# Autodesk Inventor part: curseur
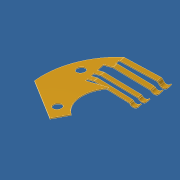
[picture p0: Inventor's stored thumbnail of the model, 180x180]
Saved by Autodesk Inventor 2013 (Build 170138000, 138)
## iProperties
Created: 2011-07
Part Number: curseur
Document SubType Name: Tôlerie
Designer: didierf
Density: 8.47 g/cm^3
Material: Laiton (jaune doux)
Mass: 0.0357038 g
Surface Area: 0.921068 cm^2
Volume: 0.00421532 cm^3
Sheet Metal Rule: Par défaut
Author: didierf
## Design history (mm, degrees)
sketch "Esquisse3"
  geometry: L1 (-14.379, 11.345)-(1.25, 18.566); L2 (1.25, 18.566)-(10.479, -1.409); L3 (10.479, -1.409)-(-5.149, -8.63); L4 (-5.149, -8.63)-(-14.379, 11.345); L5 (4.506, -11.411)-(4.506, -32.563); 1 other entity
  constraints: 2 end point, 1 vertical, 2 other
  dimensions: "d19" = 17.216 distance of L1.start L1.end; "d84" = 24.7991 deg angle of L5 L4
  node "Image2"
sketch "tracé"
  geometry: L1 (3.886, -3.147)-(6.941, 0.626); L2 (0, -41.976)-(0, 8.25); L3 (-3.534, -3.184)-(-5.423, -0.851); L4 (-5.774, -0.814)-(-6.941, 0.626); L5 (0, 0)-(-3.552, -3.519); C1 r 2.5 at (0, 0); C2 r 0.5 at (4.25, -0.7); C3 r 0.5 at (4.25, 5.1); C4 r 2.95 at (0, 0); C5 r 0.96 at (3, 4); A1 r 5 centre (0, 0) between (-3.552, -3.519) and (3.886, -3.147); A2 r 8.25 centre (0, 0) between (7.243, 3.95) and (-7.243, 3.95); A3 r 3 centre (-4.609, 2.514) between (-7.243, 3.95) and (-6.941, 0.626); A4 r 3 centre (4.609, 2.514) between (6.941, 0.626) and (7.243, 3.95); A5 r 0.25 centre (-3.728, -3.341) between (-3.552, -3.519) and (-3.534, -3.184); A6 r 0.25 centre (-5.617, -1.009) between (-5.423, -0.851) and (-5.774, -0.814); A7 r 7.95 centre (0, 0) between (7.603, 2.323) and (-7.603, 2.323); 1 further point
  constraints: 17 point on circle, 12 centre point, 10 end point, 9 tangent, 5 coincident, 1 parallel, 1 point on line, 1 vertical
  dimensions: "d53" = 10 diameter of A1; "d54" = 5 diameter of C1; "d57" = 8.25 radius of A2; "d60" = 6 diameter of A3; "d61" = 6 diameter of A4; "d66" = 78 deg angle of L1 L4; "d67" = 0.25 radius of A5; "d68" = 0.25 radius of A6; "d69" = 0.25 distance between parallel lines of L4 L3; "d70" = 3.5 distance of L4.start L5.end; "d71" = 39 deg angle of L1 L2 (derived); "d104" = 1 diameter of C2; "d105" = 1 diameter of C3; "d106" = 4.25 horizontal distance of C2.centre point (0, 0); "d107" = 0.7 vertical distance of C2.centre point (0, 0); "d108" = 5.8 distance of C2.centre C3.centre; "d109" = 4.25 horizontal distance of C3.centre point (0, 0) (derived); "d110" = 0.3 radial gap between concentric circles of A7 A2; "d114" = 5.9 diameter of C4; "d115" = 1.92 diameter of C5; "d117" = 3 distance from line of C5.centre L2; "d120" = 4 vertical distance of C5.centre point (0, 0)
sketch "piece_a_plat"
  geometry: L1 (1.033, 3.091)-(3.317, 3.6); L2 (3.317, 3.6)-(3.244, 3.926); L3 (3.244, 3.926)-(-1.948, 2.769); L4 (2.7, 6.366)-(-2.98, 5.101); L5 (-3.587, 6.707)-(1.418, 7.822); L6 (-2.489, 4.186)-(2.918, 5.39); L7 (1.642, 7.258)-(-3.457, 6.121); L8 (1.751, 6.77)-(-3.111, 5.686); L9 (1.751, 6.77)-(1.642, 7.258); L10 (-3.587, 6.707)-(-3.457, 6.121); L11 (-3.111, 5.686)-(-2.98, 5.101); L12 (3.135, 4.414)-(-2.056, 3.258); L13 (3.026, 4.902)-(-2.38, 3.698); L14 (1.277, 6.049)-(1.146, 6.635); L15 (1.037, 7.123)-(0.907, 7.709); L16 (-2.489, 4.186)-(-2.38, 3.698); L17 (-2.056, 3.258)-(-1.948, 2.769); L18 (2.918, 5.39)-(2.7, 6.366); L19 (2.57, 3.776)-(2.462, 4.264); L20 (2.353, 4.752)-(2.244, 5.24); L21 (3.317, 3.6)-(3.244, 3.926); L22 (3.135, 4.414)-(3.026, 4.902); L23 (7.51, 2.609)-(4.243, -2.596); L24 (4.243, -2.596)-(2.68, -1.616); L25 (1.033, 3.091)-(1.066, 2.942); L26 (-2.649, 6.916)-(-2.518, 6.331); L27 (-2.159, 5.898)-(-2.028, 5.313); L28 (-1.515, 4.403)-(-1.407, 3.915); L29 (-1.089, 3.473)-(-0.98, 2.985); L30 (-3.587, 6.707)-(-2.649, 6.916); L31 (-2.056, 3.258)-(-1.089, 3.473); L32 (-3.118, 6.812)-(-2.988, 6.226); L33 (-2.633, 5.793)-(-2.503, 5.207); L34 (-1.995, 4.296)-(-1.886, 3.808); L35 (-1.573, 3.365)-(-1.464, 2.877); C1 r 0.5 at (4.25, 5.1) reference; C2 r 0.5 at (4.25, 5.1); C3 r 0.5 at (4.25, -0.7) reference; C4 r 0.5 at (4.25, -0.7); A1 r 7.95 centre (0, 0) between (7.603, 2.323) and (-7.603, 2.323) reference; A2 r 7.95 centre (0, 0) between (7.51, 2.609) and (1.418, 7.822); A3 r 3.129 centre (0, 0) between (2.68, -1.616) and (1.066, 2.942); A4 r 3.129 centre (0, 0) between (-0.561, 3.079) and (-0.799, 3.025)
  constraints: 70 end point, 24 perpendicular, 24 point on line, 16 parallel, 7 point on circle, 5 centre point, 4 coincident, 3 concentric, 2 midpoint
  dimensions: "d145" = 0.6 distance of L5.start L7.end; "d146" = 0.6 distance of L8.end L4.end; "d147" = 0.5 distance of L6.start L13.end; "d148" = 0.5 distance of L12.end L3.end; "d222" = 1 distance between parallel lines of L6 L4; "d223" = 0.5 distance between parallel lines of L12 L13; "d224" = 0.5 distance between parallel lines of L7 L8
node "aplat"
feature "Pliage1patte1" dims "d150" = 0.1 (derived), "d151" = 0.05 (derived), "d152" = 0.2 (derived), "d153" = 0.1 (derived), "d154" = 3.42085, "d155" = 0.1 (derived), "Epaisseur" = 0.1, "JeuJointure" = 0.01
feature "Pliage1patte2" dims "d229" = 0.1 (derived), "d230" = 0.05 (derived), "d231" = 0.2 (derived), "d232" = 0.1 (derived), "d233" = 3.23759, "d234" = 0.1 (derived), "Epaisseur" = 0.1, "JeuJointure" = 0.01
sketch "Esquisse6"
  geometry: L1 (4.604, -0.5)-(4.604, 0) reference; L2 (4.604, 0)-(0, 0) reference; L3 (0, 0)-(0, -0.5) reference; L4 (0, -0.5)-(1.177, -0.5) reference; L5 (1.421, -0.5)-(4.604, -0.5) reference; L6 (1, 0)-(1, -0.5); A1 r 3.129 centre (1.299, -3.627) between (1.421, -0.5) and (1.177, -0.5) reference
  constraints: 2 end point, 2 point on line, 1 perpendicular
  dimensions: "d235" = 1 distance between parallel lines of L6 L3
feature "Pliage2patte1" sketch "Esquisse6" dims "d158" = 0.1 (derived), "d159" = 0.05 (derived), "d160" = 0.2 (derived), "d161" = 0.1 (derived), "d162" = 45 deg, "d163" = 0.1 (derived), "Epaisseur" = 0.1, "JeuJointure" = 0.01
sketch "Esquisse7"
  geometry: L1 (0, 0)-(0.943, 0) reference; L2 (0, 0.5)-(0, 0) reference; L3 (0.5, 0.5)-(0.5, 0); L4 (0.943, 0.5)-(0, 0.5) reference
  constraints: 2 end point, 2 point on line, 1 parallel
  dimensions: "d164" = 0.5 distance between parallel lines of L3 L2
feature "Pliage3patte1" sketch "Esquisse7" dims "d165" = 0.1 (derived), "d166" = 0.05 (derived), "d167" = 0.2 (derived), "d168" = 0.1 (derived), "d169" = 110 deg, "d170" = 0.4, "Epaisseur" = 0.1, "JeuJointure" = 0.01
sketch "Esquisse8"
  geometry: L1 (4.826, -0.5)-(4.826, 0) reference; L2 (4.826, 0)-(0, 0) reference; L3 (0, 0)-(0, -0.5) reference; L4 (0, -0.5)-(4.826, -0.5) reference; L5 (1, 0)-(1, -0.5)
  constraints: 2 end point, 2 point on line, 1 perpendicular
  dimensions: "d236" = 1 distance between parallel lines of L3 L5
feature "Pliage2patte2" sketch "Esquisse8" dims "d172" = 0.1 (derived), "d173" = 0.05 (derived), "d174" = 0.2 (derived), "d175" = 0.1 (derived), "d176" = 45 deg, "d177" = 0.1 (derived), "Epaisseur" = 0.1, "JeuJointure" = 0.01
sketch "Esquisse9"
  geometry: L1 (0.943, 0)-(0, 0) reference; L2 (0.943, 0.5)-(0.943, 0) reference; L3 (0, 0.5)-(0.943, 0.5) reference; L4 (0.443, 0)-(0.443, 0.5)
  constraints: 2 end point, 2 point on line, 1 perpendicular
  dimensions: "d237" = 0.5 distance between parallel lines of L2 L4
feature "Pliage3patte2" sketch "Esquisse9" dims "d179" = 0.1 (derived), "d180" = 0.05 (derived), "d181" = 0.2 (derived), "d182" = 0.1 (derived), "d183" = 110 deg, "d184" = 0.4, "Epaisseur" = 0.1, "JeuJointure" = 0.01
sketch "Esquisse10"
  geometry: L1 (-2.298, 6.061)-(-1.938, 5.581) reference; L2 (-6.177, 3.15)-(-5.817, 2.67); L3 (-2.763, 7.087)-(-2.403, 6.607) reference; L4 (-6.837, 4.03)-(-6.477, 3.55); L5 (-1.938, 5.581)-(-6.593, 2.088) reference; L6 (-6.282, 3.071)-(-2.298, 6.061) reference; L7 (-2.403, 6.607)-(-6.582, 3.471) reference; L8 (-6.865, 4.009)-(-2.763, 7.087) reference
  constraints: 4 end point, 4 point on line, 2 parallel, 1 collinear, 1 perpendicular
  dimensions: "d185" = 4.85 distance between parallel lines of L2 L1
feature "Pliage1patte3" dims "d186" = 0.1 (derived), "d187" = 0.05 (derived), "d188" = 0.2 (derived), "d189" = 0.1 (derived), "d190" = 3.23759, "d191" = 0.1 (derived), "Epaisseur" = 0.1, "JeuJointure" = 0.01
sketch "Esquisse11"
  geometry: L1 (4.827, 0.6)-(4.827, 0) reference; L2 (3.827, 0.6)-(3.827, 0)
  constraints: 2 end point, 1 parallel
  dimensions: "d192" = 1 distance between parallel lines of L2 L1
feature "Pliage2patte3" sketch "Esquisse11" dims "d193" = 0.1 (derived), "d194" = 0.05 (derived), "d195" = 0.2 (derived), "d196" = 0.1 (derived), "d197" = 45 deg, "d198" = 0.1 (derived), "Epaisseur" = 0.1, "JeuJointure" = 0.01
sketch "Esquisse12"
  geometry: L1 (0.943, 0.6)-(0.943, 0) reference; L2 (0.443, 0.6)-(0.443, 0)
  constraints: 2 end point, 1 parallel
  dimensions: "d199" = 0.5 distance between parallel lines of L2 L1
feature "Pliage3patte3" sketch "Esquisse12" dims "d200" = 0.1 (derived), "d201" = 0.05 (derived), "d202" = 0.2 (derived), "d203" = 0.1 (derived), "d204" = 110 deg, "d205" = 0.4, "Epaisseur" = 0.1, "JeuJointure" = 0.01
feature "Pliage1patte4" dims "d238" = 0.1 (derived), "d239" = 0.05 (derived), "d240" = 0.2 (derived), "d241" = 0.1 (derived), "d242" = 2.64417, "d243" = 0.1 (derived), "Epaisseur" = 0.1, "JeuJointure" = 0.01
sketch "Esquisse13"
  geometry: L1 (4.773, 0.6)-(4.773, 0); L2 (3.773, 0.6)-(3.773, 0); L3 (0, 0.6)-(0, 0) reference; L4 (5.074, 0)-(0, 0) reference; L5 (5.074, 0.6)-(5.074, 0) reference; L6 (0, 0.6)-(5.074, 0.6) reference
  constraints: 4 end point, 1 parallel
  dimensions: "d206" = 1 distance between parallel lines of L2 L1
feature "Pliage2patte4" sketch "Esquisse13" dims "d207" = 0.1 (derived), "d208" = 0.05 (derived), "d209" = 0.2 (derived), "d210" = 0.1 (derived), "d211" = 45 deg, "d212" = 0.1 (derived), "Epaisseur" = 0.1, "JeuJointure" = 0.01
sketch "Esquisse14"
  geometry: L1 (1.244, 0.6)-(1.244, 0) reference; L2 (0.744, 0.6)-(0.744, 0)
  constraints: 2 end point, 1 parallel
  dimensions: "d213" = 0.5 distance between parallel lines of L2 L1
feature "Pliage3patte4" sketch "Esquisse14" dims "d214" = 0.1 (derived), "d215" = 0.05 (derived), "d216" = 0.2 (derived), "d217" = 0.1 (derived), "d218" = 110 deg, "d219" = 0.4, "Epaisseur" = 0.1, "JeuJointure" = 0.01
node "Plan de construction5"
node "Solide1"
node "Corps solides"
node "Corps surfaciques"
feature "Plaque1" dims "Epaisseur" = 0.1
node "Boucle projetée1"
node "Boucle projetée2"
other parameters: "d52" = 78 deg, "d62" = 0.25, "d63" = 0.25, "RayonPli" = 0.1 (derived), "LargeurGrugeage" = 0.1 (derived), "ProfondeurGrugeage" = 0.05 (derived), "TailleGrugeage" = 0.4 (derived), "RestesMinimum" = 0.2 (derived), "Rayondetransition" = 0.1 (derived), "TailleRayonJacobi" = 0.1 (derived), "d149" = 0.1 (derived), "d228" = 1.55, "TailleJeu" = 0.1 (derived)
